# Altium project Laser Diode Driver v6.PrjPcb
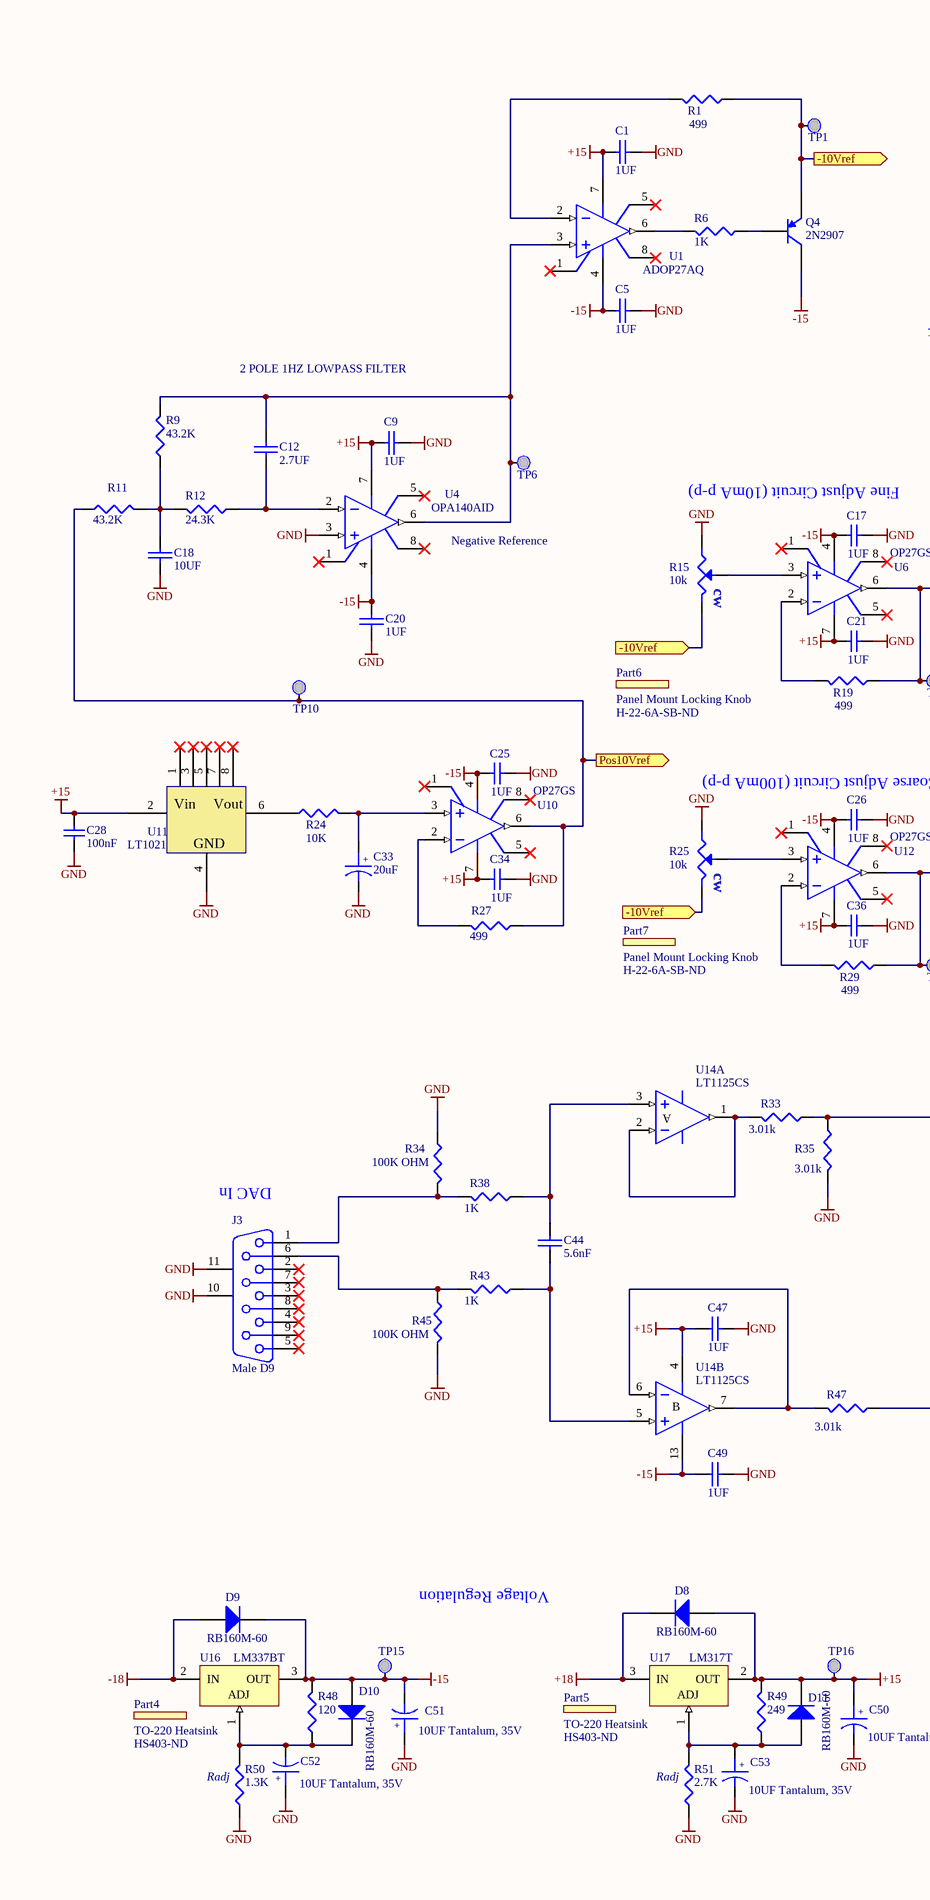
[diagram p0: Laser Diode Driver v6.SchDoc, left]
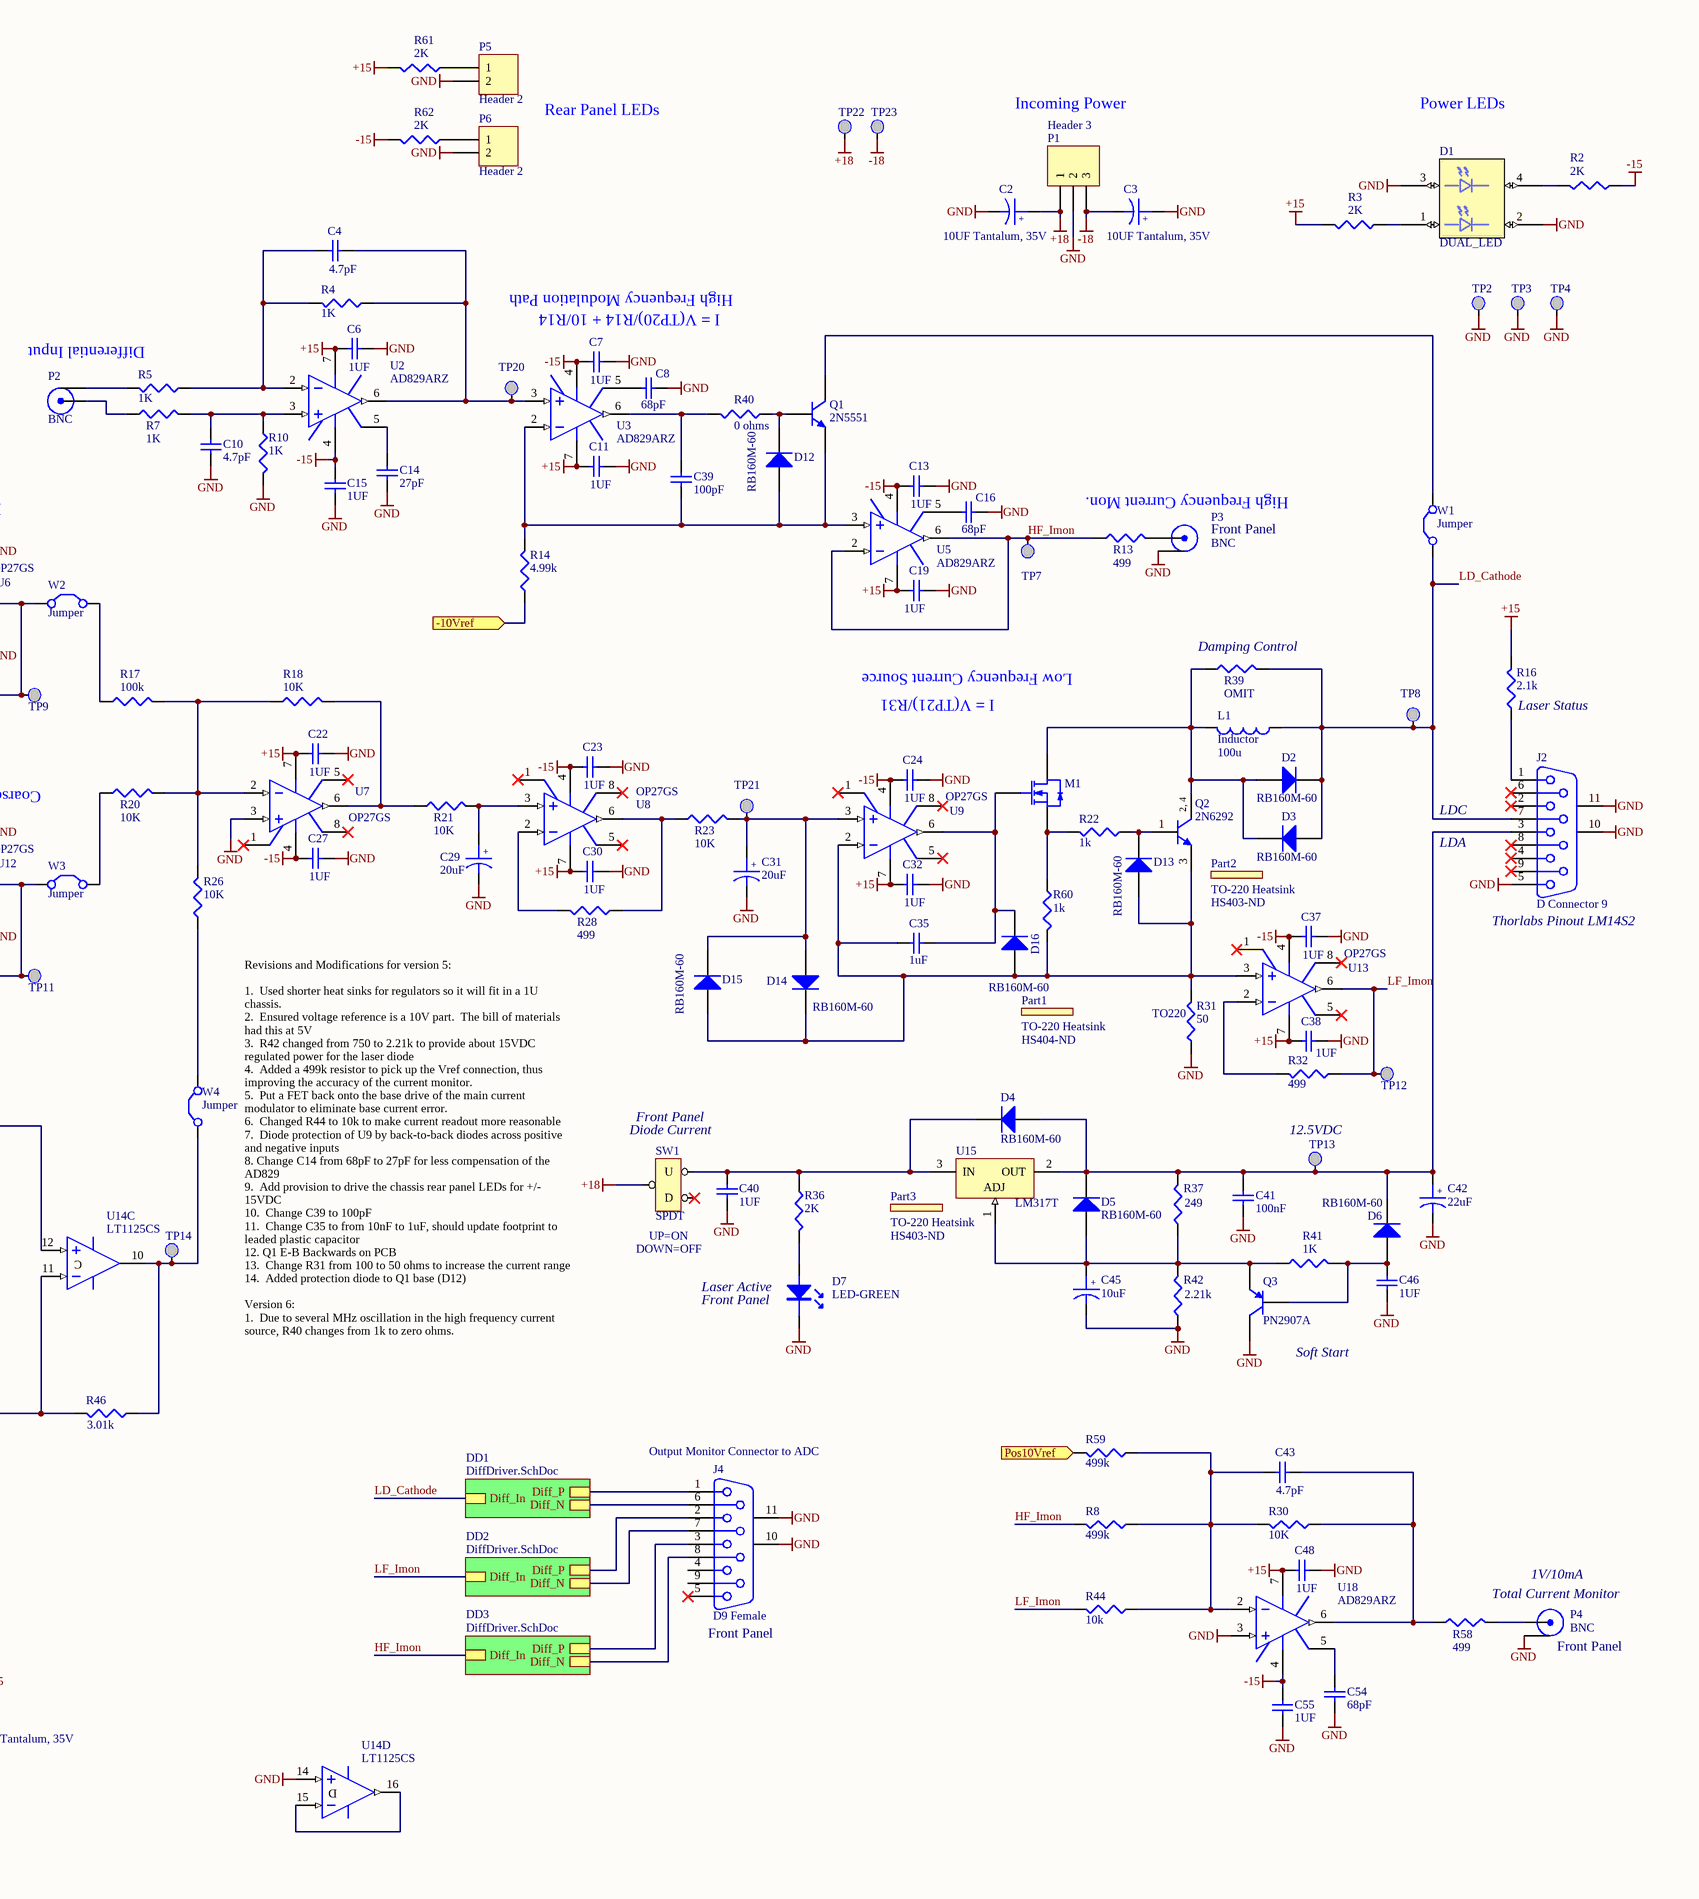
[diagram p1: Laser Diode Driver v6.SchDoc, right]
2 sheets, 224 parts. Net scope: hierarchical (ports join the sheet entries above them; power ports are global).
Board file: Laser Diode Driver v5.PcbDoc
Sheets:
  Laser Diode Driver v6.SchDoc
    DD1 = DiffDriver.SchDoc
    DD2 = DiffDriver.SchDoc
    DD3 = DiffDriver.SchDoc

## Sheet Laser Diode Driver v6.SchDoc: Laser Current Driver
size C; PageSetup: Record=PageOptions|CenterHorizontal=True|CenterVertical=True|PrintScale=0.70|XCorrection=1.00|YCorrection=1.00|PrintKind=0|BorderSize=5000000|LeftOffset=0|BottomOffset=0|Orientation=2|PaperLength=1000|PaperWidth=1000|Scale=100|PaperSource=15|PrintQuality=600|MediaType=1|DitherType=10|PaperKind=11x17|PrintScaleMode=1; Organization: LIGO Laboratory; Address1: California Institute of Technology; Address2: Massachusetts Institute of Technology; DocumentNumber: D1200719; Revision: V5; SheetNumber: 1; SheetTotal: 2; Engineer: R.S. Abbott

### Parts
C1  1UF  [3216[1206]]
C2  10UF Tantalum, 35V  [7343-31]
C3  10UF Tantalum, 35V  [7343-31]
C4  4.7pF  [3216[1206]]
C5  1UF  [3216[1206]]
C6  1UF  [3216[1206]]
C7  1UF  [3216[1206]]
C8  68pF  [3216[1206]]
C9  1UF  [3216[1206]]
C10  4.7pF  [3216[1206]]
C11  1UF  [3216[1206]]
C12  2.7UF  [ECQ-E1275KF]
C13  1UF  [3216[1206]]
C14  27pF  [3216[1206]]
C15  1UF  [3216[1206]]
C16  68pF  [3216[1206]]
C17  1UF  [3216[1206]]
C18  10UF  [ECQ-E1106KF_Side]
C19  1UF  [3216[1206]]
C20  1UF  [3216[1206]]
C21  1UF  [3216[1206]]
C22  1UF  [3216[1206]]
C23  1UF  [3216[1206]]
C24  1UF  [3216[1206]]
C25  1UF  [3216[1206]]
C26  1UF  [3216[1206]]
C27  1UF  [3216[1206]]
C28  100nF  [3216[1206]]
C29  20uF  [AmCap_20UF]
C30  1UF  [3216[1206]]
C31  20uF  [AmCap_20UF]
C32  1UF  [3216[1206]]
C33  20uF  [AmCap_20UF]
C34  1UF  [3216[1206]]
C35  1uF  [ECQ-E1105KF]
C36  1UF  [3216[1206]]
C37  1UF  [3216[1206]]
C38  1UF  [3216[1206]]
C39  100pF  [3216[1206]]
C40  1UF  [3216[1206]]
C41  100nF  [3216[1206]]
C42  22uF  [7343-31]
C43  4.7pF  [3216[1206]]
C44  5.6nF  [3216[1206]]
C45  10uF  [7343-31]
C46  1UF  [3216[1206]]
C47  1UF  [3216[1206]]
C48  1UF  [3216[1206]]
C49  1UF  [3216[1206]]
C50  10UF Tantalum, 35V  [6032]
C51  10UF Tantalum, 35V  [6032]
C52  10UF Tantalum, 35V  [6032]
C53  10UF Tantalum, 35V  [6032]
C54  68pF  [3216[1206]]
C55  1UF  [3216[1206]]
D1  DUAL_LED  [my LUMEX Dual LED]
D2  RB160M-60  [SOD123]
D3  RB160M-60  [SOD123]
D4  RB160M-60  [SOD123]
D5  RB160M-60  [SOD123]
D6  RB160M-60  [SOD123]
D7  LED-GREEN  [LED_RA]
D8  RB160M-60  [SOD123]
D9  RB160M-60  [SOD123]
D10  RB160M-60  [SOD123]
D11  RB160M-60  [SOD123]
D12  RB160M-60  [SOD123]
D13  RB160M-60  [SOD123]
D14  RB160M-60  [SOD123]
D15  RB160M-60  [SOD123]
D16  RB160M-60  [SOD123]
J2  D Connector 9  [MY_DB9F_RA]
J3  Male D9  [MY_DB9M_RA]
J4  D9 Female  [MY_DB9F_RA]
L1  Inductor  value 100u  [CDRH127]
M1  NMOS  [SOT416-3L]  (value not drawn)
P1  Header 3  [Molex_156_RA_3]
P2  BNC  [MY_BNC_RA CON]
P3  BNC  [MY_BNC_RA CON]
P4  BNC  [MY_BNC_RA CON]
P5  Header 2  [MOLEX_156_RA_2]
P6  Header 2  [MOLEX_156_RA_2]
Part1  TO-220 Heatsink  Digikey Part Number: HS404-ND  (mechanical)
Part2  TO-220 Heatsink  Digikey Part Number: HS403-ND  (mechanical)
Part3  TO-220 Heatsink  Digikey Part Number: HS403-ND  (mechanical)
Part4  TO-220 Heatsink  Digikey Part Number: HS403-ND  (mechanical)
Part5  TO-220 Heatsink  Digikey Part Number: HS403-ND  (mechanical)
Part6  Panel Mount Locking Knob  Digikey Part Number: H-22-6A-SB-ND  (mechanical)
Part7  Panel Mount Locking Knob  Digikey Part Number: H-22-6A-SB-ND  (mechanical)
Q1  2N5551  [SOT-23]
Q2  2N6292  [HS403-ND]
Q3  PN2907A  [sot-23 3906]
Q4  2N2907  [sot-23 3906]
R1  499  [3216[1206]]
R2  2K  [3216[1206]]
R3  2K  [3216[1206]]
R4  1K  [3216[1206]]
R5  1K  [3216[1206]]
R6  1K  [3216[1206]]
R7  1K  [3216[1206]]
R8  499k  [3216[1206]]
R9  43.2K  [3216[1206]]
R10  1K  [3216[1206]]
R11  43.2K  [3216[1206]]
R12  24.3K  [3216[1206]]
R13  499  [3216[1206]]
R14  4.99k  [3216[1206]]
R15  10k  [Bournes Pot]
R16  2.1k  [3216[1206]]
R17  100k  [3216[1206]]
R18  10K  [3216[1206]]
R19  499  [3216[1206]]
R20  10K  [3216[1206]]
R21  10K  [3216[1206]]
R22  1k  [3216[1206]]
R23  10K  [3216[1206]]
R24  10K  [3216[1206]]
R25  10k  [Bournes Pot]
R26  10K  [3216[1206]]
R27  499  [3216[1206]]
R28  499  [3216[1206]]
R29  499  [3216[1206]]
R30  10K  [3216[1206]]
R31  value 50  [AAVID TO220 Heatsink_2pin]  (hidden comment: Res3)
R32  499  [3216[1206]]
R33  3.01k  [3216[1206]]
R34  100K OHM  [3216[1206]]
R35  3.01k  [3216[1206]]
R36  2K  [3216[1206]]
R37  249  [3216[1206]]
R38  1K  [3216[1206]]
R39  OMIT  [3216[1206]]
R40  0 ohms  [3216[1206]]
R41  1K  [3216[1206]]
R42  2.21k  [3216[1206]]
R43  1K  [3216[1206]]
R44  10k  [3216[1206]]
R45  100K OHM  [3216[1206]]
R46  3.01k  [3216[1206]]
R47  3.01k  [3216[1206]]
R48  120  [3216[1206]]
R49  249  [3216[1206]]
R50  1.3K  [3216[1206]]
R51  2.7K  [3216[1206]]
R58  499  [3216[1206]]
R59  499k  [3216[1206]]
R60  1k  [3216[1206]]
R61  2K  [3216[1206]]
R62  2K  [3216[1206]]
SW1  SPDT  [my_ra_spdt]
TP1  TESTPT  [smt_tp]  (value not drawn)
TP2  TESTPT  [smt_tp]  (value not drawn)
TP3  TESTPT  [smt_tp]  (value not drawn)
TP4  TESTPT  [smt_tp]  (value not drawn)
TP6  TESTPT  [smt_tp]  (value not drawn)
TP7  TESTPT  [smt_tp]  (value not drawn)
TP8  TESTPT  [smt_tp]  (value not drawn)
TP9  TESTPT  [smt_tp]  (value not drawn)
TP10  TESTPT  [smt_tp]  (value not drawn)
TP11  TESTPT  [smt_tp]  (value not drawn)
TP12  TESTPT  [smt_tp]  (value not drawn)
TP13  TESTPT  [smt_tp]  (value not drawn)
TP14  TESTPT  [smt_tp]  (value not drawn)
TP15  TESTPT  [smt_tp]  (value not drawn)
TP16  TESTPT  [smt_tp]  (value not drawn)
TP20  TESTPT  [smt_tp]  (value not drawn)
TP21  TESTPT  [smt_tp]  (value not drawn)
TP22  TESTPT  [smt_tp]  (value not drawn)
TP23  TESTPT  [smt_tp]  (value not drawn)
U1  ADOP27AQ  [SO8_M]
U2  value AD829ARZ  [SOIC127P600-8N]  (hidden comment: AD829)
U3  value AD829ARZ  [SOIC127P600-8N]  (hidden comment: AD829)
U4  OPA140AID  [SO8_M]
U5  value AD829ARZ  [SOIC127P600-8N]  (hidden comment: AD829)
U6  OP27GS  [SO-8_N]
U7  OP27GS  [SO-8_N]
U8  OP27GS  [SO-8_N]
U9  OP27GS  [SO-8_N]
U10  OP27GS  [SO-8_N]
U11  LT1021  [SO-8]
U12  OP27GS  [SO-8_N]
U13  OP27GS  [SO-8_N]
U14  LT1125CS  [SOIC127P1030-16N]  (parts A,B,C,D of 4)
U15  LM317T  [HS403-ND]
U16  LM337BT  [HS403-ND]
U17  LM317T  [HS403-ND]
U18  value AD829ARZ  [SOIC127P600-8N]  (hidden comment: AD829)
W1  Jumper  [HDR1X3]
W2  Jumper  [HDR1X3]
W3  Jumper  [HDR1X3]
W4  Jumper  [HDR1X3]

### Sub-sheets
DD1 = DiffDriver.SchDoc: Diff_P, Diff_N, Diff_In
DD2 = DiffDriver.SchDoc: Diff_P, Diff_N, Diff_In
DD3 = DiffDriver.SchDoc: Diff_P, Diff_N, Diff_In

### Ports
-10Vref, Pos10Vref

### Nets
+15: C1.2 C6.2 C9.1 C11.2 C19.2 C21.2 C22.2 C28.2 C30.2 C32.2 C34.2 C36.2 C38.2 C47.1 C48.2 C50.1 D8.1(A) D11.2(K) R3.2 R16.2 R49.2 R61.2 TP16.1 U1.7(V+) U2.7(V+) U3.7(V+) U4.7(V+) U5.7(V+) U6.7(V+) U7.7(V+) U8.7(V+) U9.7(V+) U10.7(V+) U11.2 U12.7(V+) U13.7(V+) U14.4(V+) U17.2(OUT) U18.7(V+)
+18: C2.1 D8.2(K) P1.1 SW1.2 TP22.1 U17.3(IN)
-15: C5.2 C7.2 C13.2 C15.2 C17.2 C20.1 C23.2 C24.2 C25.2 C26.2 C27.2 C37.2 C49.1 C51.2 C55.2 D9.2(K) D10.1(A) Q4.3(C) R2.1 R48.2 R62.2 TP15.1 U1.4(V-) U2.4(V-) U3.4(V-) U4.4(V-) U5.4(V-) U6.4(V-) U7.4(V-) U8.4(V-) U9.4(V-) U10.4(V-) U12.4(V-) U13.4(V-) U14.13(V-) U16.3(OUT) U18.4(V-)
-18: C3.2 D9.1(A) P1.3 TP23.1 U16.2(IN)
GND: C1.1 C2.2 C3.1 C5.1 C6.1 C7.1 C8.1 C9.2 C10.1 C11.1 C13.1 C14.1 C15.1 C16.1 C17.1 C18.2 C19.1 C20.2 C21.1 C22.1 C23.1 C24.1 C25.1 C26.1 C27.1 C28.1 C29.2 C30.1 C31.2 C32.1 C33.2 C34.1 C36.1 C37.1 C38.1 C40.2 C41.2 C42.2 C45.2 C46.2 C47.2 C48.1 C49.2 C50.2 C51.1 C52.1 C53.2 C54.1 C55.1 D1.2 D1.3 D7.K J2.5 J2.10(MH1) J2.11(MH2) J3.10(MH1) J3.11(MH2) J4.10(MH1) J4.11(MH2) P1.2 P3.2 P4.2 P5.2 P6.2 Q3.3(C) R10.2 R15.1 R25.1 R31.1 R34.1 R35.2 R42.1 R45.2 R50.1 R51.1 TP2.1 TP3.1 TP4.1 U4.3(IN+) U7.3(IN+) U11.4 U14.14(IN+) U18.3(IN+)
HF_Imon: R8.2 R13.1 TP7.1 U5.2(IN-) U5.6(OUT) ; sheet DD3/Diff_In
LD_Cathode: D2.2(K) D3.1(A) J2.7 L1.1 R39.2 TP8.1 W1.1(C1) ; sheet DD1/Diff_In
LF_Imon: R32.1 R44.2 TP12.1 U13.6(OUT) ; sheet DD2/Diff_In
NetC4_1: C4.1 R4.1 TP20.1 U2.6(OUT) U3.3(IN+)
NetC4_2: C4.2 R4.2 R5.1 U2.2(IN-)
NetC8_2: C8.2 U3.5(NUL)
NetC10_2: C10.2 R7.2 R10.1 U2.3(IN+)
NetC12_1: C12.1 R9.2 TP6.1 U1.3(IN+) U4.6(OUT)
NetC12_2: C12.2 R12.1 U4.2(IN-)
NetC14_2: C14.2 U2.5(NUL)
NetC16_2: C16.2 U5.5(NUL)
NetC18_1: C18.1 R9.1 R11.2 R12.2
NetC29_1: C29.1 R21.2 U8.3(IN+)
NetC31_1: C31.1 D14.1(A) D15.2(K) R23.2 TP21.1 U9.3(IN+)
NetC33_1: C33.1 R24.2 U10.3(IN+)
NetC35_1: C35.1 D13.1(A) D14.2(K) D15.1(A) D16.1(A) Q2.3(E) R31.2 R60.2 U9.2(IN-) U13.3(IN+)
NetC35_2: C35.2 D16.2(K) M1.1(G) U9.6(OUT)
NetC39_1: C39.1 R40.2 U3.6(OUT)
NetC39_2: C39.2 D12.1(A) Q1.2(E) R14.2 U3.2(IN-) U5.3(IN+)
NetC40_1: C40.1 D4.2(K) R36.1 SW1.1(U) U15.3(IN)
NetC41_1: C41.1 C42.1 D4.1(A) D5.2(K) D6.2(K) J2.3 R37.2 TP13.1 U15.2(OUT)
NetC43_1: C43.1 R30.1 R58.1 U18.6(OUT)
NetC43_2: C43.2 R8.1 R30.2 R44.1 R59.1 U18.2(IN-)
NetC44_1: C44.1 R43.1 U14.5(IN+)
NetC44_2: C44.2 R38.1 U14.3(IN+)
NetC45_1: C45.1 D5.1(A) Q3.1(E) R37.1 R41.1 R42.2 U15.1(ADJ)
NetC46_1: C46.1 D6.1(A) Q3.2(B) R41.2
NetC52_2: C52.2 D10.2(K) R48.1 R50.2 U16.1(ADJ)
NetC53_1: C53.1 D11.1(A) R49.1 R51.2 U17.1(ADJ)
NetC54_2: C54.2 U18.5(NUL)
NetD1_1: D1.1 R3.1
NetD1_4: D1.4 R2.2
NetD2_1: D2.1(A) D3.2(K) L1.2 M1.3(D) Q2.2(C) R39.1
NetD7_A: D7.A R36.2
NetD12_2: D12.2(K) Q1.1(B) R40.1
NetD13_2: D13.2(K) Q2.1(B) R22.1
NetJ2_1: J2.1 R16.1
NetJ3_1: J3.1 R34.2 R38.2
NetJ3_6: J3.6 R43.2 R45.1
NetJ4_1: J4.1 ; sheet DD1/Diff_P
NetJ4_2: J4.2 ; sheet DD2/Diff_P
NetJ4_3: J4.3 ; sheet DD3/Diff_P
NetJ4_6: J4.6 ; sheet DD1/Diff_N
NetJ4_7: J4.7 ; sheet DD2/Diff_N
NetJ4_8: J4.8 ; sheet DD3/Diff_N
NetM1_2: M1.2(S) R22.2 R60.1
NetP2_1: P2.1 R7.1
NetP2_2: P2.2 R5.2
NetP3_1: P3.1 R13.2
NetP4_1: P4.1 R58.2
NetP5_1: P5.1 R61.1
NetP6_1: P6.1 R62.1
NetQ1_3: Q1.3(C) W1.2(C2)
NetQ4_1: Q4.1(E) R1.1 R14.1 R15.3 R25.3 TP1.1 ; port -10Vref
NetQ4_2: Q4.2(B) R6.1
NetR1_2: R1.2 U1.2(IN-)
NetR6_2: R6.2 U1.6(OUT)
NetR11_1: R11.1 R27.1 R59.2 TP10.1 U10.6(OUT) ; port Pos10Vref
NetR15_2: R15.2 U6.3(IN+)
NetR17_1: R17.1 W2.2(C2)
NetR17_2: R17.2 R18.1 R20.2 R26.2 U7.2(IN-)
NetR18_2: R18.2 R21.1 U7.6(OUT)
NetR19_1: R19.1 TP9.1 U6.6(OUT) W2.1(C1)
NetR19_2: R19.2 U6.2(IN-)
NetR20_1: R20.1 W3.2(C2)
NetR23_1: R23.1 R28.1 U8.6(OUT)
NetR24_1: R24.1 U11.6
NetR25_2: R25.2 U12.3(IN+)
NetR26_1: R26.1 W4.2(C2)
NetR27_2: R27.2 U10.2(IN-)
NetR28_2: R28.2 U8.2(IN-)
NetR29_1: R29.1 TP11.1 U12.6(OUT) W3.1(C1)
NetR29_2: R29.2 U12.2(IN-)
NetR32_2: R32.2 U13.2(IN-)
NetR33_1: R33.1 R35.1 U14.12(IN+)
NetR33_2: R33.2 U14.1(OUT) U14.2(IN-)
NetR46_1: R46.1 TP14.1 U14.10(OUT) W4.1(C1)
NetR46_2: R46.2 R47.1 U14.11(IN-)
NetR47_2: R47.2 U14.6(IN-) U14.7(OUT)
NetU14_15: U14.15(IN-) U14.16(OUT)

Not connected (* = marked no-connect by the designer): J2 2* 4* 6* 8* 9*; J3 2* 3* 4* 5* 7* 8* 9*; J4 4 5* 9; SW1 3(D)*; U1 1(NULL1)* 5(NC)* 8(NULL2)*; U2 1(NUL) 8(NC); U3 1(NUL) 8(NC); U4 1(NULL1)* 5(NC)* 8(NULL2)*; U5 1(NUL) 8(NC); U6 1(CMPEN)* 5(NC)* 8(CMPEN)*; U7 1(CMPEN)* 5(NC)* 8(CMPEN)*; U8 1(CMPEN)* 5(NC)* 8(CMPEN)*; U9 1(CMPEN)* 5(NC)* 8(CMPEN)*; U10 1(CMPEN)* 5(NC)* 8(CMPEN)*; U11 1* 3* 5* 7* 8*; U12 1(CMPEN)* 5(NC)* 8(CMPEN)*; U13 1(CMPEN)* 5(NC)* 8(CMPEN)*; U18 1(NUL) 8(NC)

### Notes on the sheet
- Rear Panel LEDs
- Incoming Power
- Power LEDs
- (near C7) I = V(TP20)/R14 + 10/R14
- High Frequency Modulation Path
- 2 POLE 1HZ LOWPASS FILTER
- Differential Input
- Fine Adjust Circuit (10mA p-p)
- (near P3) Front Panel
- High Frequency Current Mon.
- Negative Reference
- Low Frequency Current Source
- (near R39) Damping Control
- I = V(TP21)/R31
- (near R16) Laser Status
- Coarse Adjust Circuit (100mA p-p)
- LDC
- LDA
- (near J2) Thorlabs Pinout LM14S2
- (near J3) DAC In
- Diode Current
- Front Panel
- (near TP13) 12.5VDC
- (near SW1) UP=ON
- DOWN=OFF
- (near D7) Front Panel
- (near D7) Laser Active
- Revisions and Modifications for version 5:
  1.  Used shorter heat sinks for regulators so it will fit in a 1U chassis.
  2.  Ensured voltage reference is a 10V part.  The bill of materials had this at 5V
  3.  R42 changed from 750 to 2.21k to provide about 15VDC regulated power for the laser diode
  4.  Added a 499k resistor to pick up the Vref connection, thus improving the accuracy of the current monitor.
  5.  Put a FET back onto the base drive of the main current modulator to eliminate base current error.
  6.  Changed R44 to 10k to make current readout more reasonable
  7.  Diode protection of U9 by back-to-back diodes across positive and negative inputs
  8. Change C14 from 68pF to 27pF for less compensation of the AD829
  9.  Add provision to drive the chassis rear panel LEDs for +/- 15VDC
  10.  Change C39 to 100pF
  11.  Change C35 to from 10nF to 1uF, should update footprint to leaded plastic capacitor
  12. Q1 E-B Backwards on PCB
  13.  Change R31 from 100 to 50 ohms to increase the current range
  14.  Added protection diode to Q1 base (D12)
  Version 6:
  1.  Due to several MHz oscillation in the high frequency current source, R40 changes from 1k to zero ohms.
- Soft Start
- (near J4) Output Monitor Connector to ADC
- 1V/10mA
- Voltage Regulation
- (near J4) Front Panel
- Total Current Monitor
- (near P4) Front Panel
- (near R50) Radj
- (near R51) Radj

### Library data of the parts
C1 C5 C9 C12 C18 C20 = MYCAP: Checked: y
C2 C3 = CAPACITOR POL: Polarized Cap; Manufacturer: AVX Corporation; Manufacturers Part Number: TAJC106K035RNJ; Description: CAP TANTALUM 10UF 35V 10% SMD; Capacitance: 10µF; Checked: y
C4 C8 C10 C14 C16 C28 C35 C39 C43 C54 = Cap: Capacitor; Checked: y
C6 C7 C11 C13 C15 C17 C19 C21-C27 C30 C32 C34 C36-C38 C40 C46 C48 C55 = Cap: Capacitor; Checked: y; Capacitance: 1.0µF
C29 C31 C33 C42 = CAPACITOR POL: Polarized Cap; Checked: y
C41 = Cap: Capacitor
C44 = MYCAP: CAP 1.0UF 50V CERAMIC F 1206; Checked: y
C45 = CAPACITOR POL: Polarized Cap; Manufacturer: AVX Corporation; Manufacturers Part Number: TAJC106M035RNJ; Checked: y; Capacitance: 10µF
C47 C49 = MYCAP: CAP 1.0UF 50V CERAMIC F 1206; Capacitance: 1.0µF; Checked: y
C50-C53 = CAPACITOR POL: Polarized Cap; Manufacturer: AVX Corporation; Manufacturers Part Number: TAJC106M035RNJ; Description: CAP TANTALUM 10UF 35V 10% SMD; Capacitance: 10µF; Checked: y
D1 = DUAL_LED: Dual Led indicator; Checked: y
D2-D6 D12-D16 = Diode 1N4001: 1 Amp General Purpose Rectifier; Checked: y
D7 = LED: LED GREEN T1-3/4 RT ANG PCB; Checked: y
D8-D11 = Diode 1N4148: High Conductance Fast Diode; Checked: y
J2-J4 = D Connector 9: Receptacle Assembly, 9 Position, Right Angle; Checked: y
L1 = Inductor: Checked: n
M1 = 2SK3019: ROHM N-Channel MOSFET; Checked: n
P1 = Header 3: Header, 3-Pin; Checked: y
P2-P4 = BNC: Checked: y
P5 P6 = Header 2: Header, 2-Pin; Checked: y
Part1 = Mechanical Part: For BOM Only
Part2-Part7 = Mechanical Part: For BOM Only; Checked: y
Q1 = 2N5551: NPN General Purpose Amplifier; Checked: y
Q2 = FZT649: SOT223 NPN Silicon Planar High-Performance Transistor; Checked: y
Q3 = PN2907A: PNP General Purpose Amplifier; Checked: y
Q4 = 2N3906: PNP General Purpose Amplifier; Checked: y
R1-R14 R16-R24 R26-R30 R32 R36 R37 R39-R42 R44 R58-R62 = Res3: Resistor; Checked: y
R15 R25 = MPEPOT: Potentiometer; Checked: y
R31 = Res3: Resistor; Heatsink Part Number: HS404-ND; Checked: y
R33 R47 = MYRES: Resistor; Description: RES 3.01K OHM 1/4W 1% 1206 SMD; Checked: y
R34 R45 = MYRES: Resistor; Description: RES 100K OHM 1/4W .1% 1206 SMD; Checked: y
R35 R46 = MYRES: Resistor; Description: RES 1.50K OHM 1/4W 0.1% 1206; Checked: y
R38 = MYRES: Resistor; Description: VISHAY DALE - WSL120600000ZEA9 - RESISTOR, ZERO OHM JUMPER; Checked: y
R43 = MYRES: Resistor; Manufacturer: VISHAY DALE; Manufacturers Part Number: WSL120600000ZEA9; Description: VISHAY DALE - WSL120600000ZEA9 - RESISTOR, ZERO OHM JUMPER; Checked: y
R48-R51 = MYRES: Checked: y
SW1 = MY_SPDT: Rocker SPDT; Checked: y
TP1-TP4 TP6-TP16 TP20-TP23 = TESTPT: PCB Testpoint; Checked: y
U1 = ADOP27AQ: Ultra-Low Noise, Precision Operational Amplifier; Checked: y
U2 U3 U5 U18 = OP184ES: Video Operational Amplifier; Manufacturer: Analog Devices Inc; Description: IC VIDEO OPAMP HS LN 8-SOIC; Checked: y
U4 = ADOP27AQ: FET Input Operational Amplifier; Checked: y
U6-U10 U12 U13 = OP27GS: Low-Noise, Precision Operational Amplifier; Checked: y
U11 = LT1021: Precision Voltage Reference; Checked: y
U14 = LT1125CS: Quad Low Noise, High-Speed Precision Operational Amplifier; Manufacturer: LINEAR TECHNOLOGY; Manufacturers Part Number: LT1125CSW#PBF; Description: LINEAR TECHNOLOGY - LT1125CSW#PBF - IC, OP-AMP, 12.5MHZ, 4.5V/µS, SOIC-16; Checked: y
U15 U17 = LM317T: Three-Terminal Adjustable Output Positive Voltage Regulator; Checked: n
U16 = LM337BT: 3-Terminal Adjustable Negative Voltage Regulator; Checked: y
W1-W4 = Jumper: Jumper Wire; Checked: y

## Sheet DiffDriver.SchDoc: Differential Driver
size A; Organization: LIGO Laboratory; Address1: California Institute of Technology; Address2: Massachusetts Institute of Technology; Revision: V5; SheetNumber: 2; SheetTotal: 2; Engineer: R.S. Abbott
Used 3 times, as channels DD1, DD2, DD3. Parts and nets are listed once, with the designators drawn on the sheet.
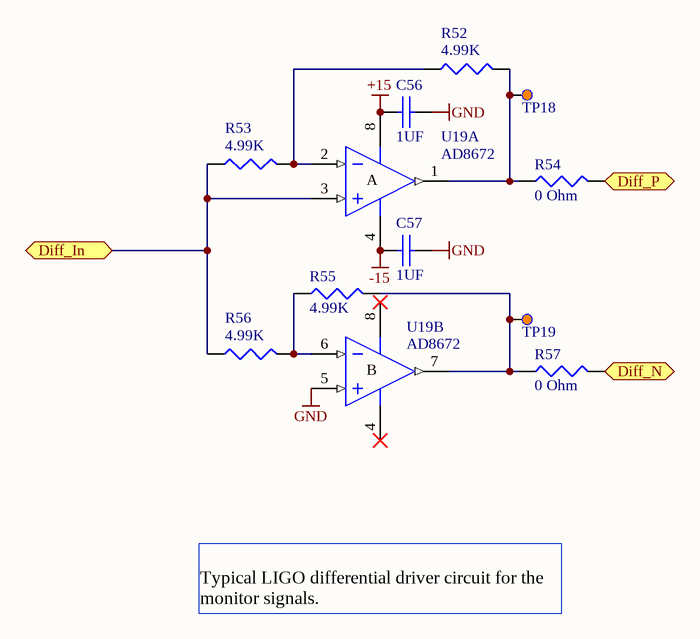
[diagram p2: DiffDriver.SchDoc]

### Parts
C56  1UF  [3216[1206]]
C57  1UF  [3216[1206]]
R52  4.99K  [3216[1206]]
R53  4.99K  [3216[1206]]
R54  0 Ohm  [3216[1206]]
R55  4.99K  [3216[1206]]
R56  4.99K  [3216[1206]]
R57  0 Ohm  [3216[1206]]
TP18  Wire Hole  [TP-hole]  (value not drawn)  (no BOM)
TP19  Wire Hole  [TP-hole]  (value not drawn)  (no BOM)
U19  AD8672  [SO8_N]  (parts A,B of 2)

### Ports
Diff_In, Diff_N, Diff_P

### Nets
+15: C56.2 U19.8(V+)
-15: C57.2 U19.4(V-)
GND: C56.1 C57.1 U19.5(IN+)
Diff_In: R53.1 R56.1 U19.3(IN+) ; port Diff_In
Diff_N: R57.2 ; port Diff_N
Diff_P: R54.2 ; port Diff_P
NetR52_1: R52.1 R53.2 U19.2(IN-)
NetR52_2: R52.2 R54.1 TP18.1 U19.1(OUT)
NetR55_1: R55.1 R56.2 U19.6(IN-)
NetR55_2: R55.2 R57.1 TP19.1 U19.7(OUT)

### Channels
DD1: designators end in _DD1; ports Diff_In=LD_Cathode Diff_N=NetJ4_6 Diff_P=NetJ4_1
DD2: designators end in _DD2; ports Diff_In=LF_Imon Diff_N=NetJ4_7 Diff_P=NetJ4_2
DD3: designators end in _DD3; ports Diff_In=HF_Imon Diff_N=NetJ4_8 Diff_P=NetJ4_3

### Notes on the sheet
- Typical LIGO differential driver circuit for the monitor signals.

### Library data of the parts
C56 C57 = MYCAP: Checked: y
R52-R57 = Res3: Resistor; Checked: y
TP18 TP19 = TestHole: Plated Hole to Solder Wire to; Checked: y
U19 = AD826AR: High-Speed, Low-Power Dual Operational Amplifier; Checked: y

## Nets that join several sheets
+15: Laser Diode Driver v6 (39 pins), DD1 (C56_DD1.2 U19_DD1.8), DD2 (C56_DD2.2 U19_DD2.8), DD3 (C56_DD3.2 U19_DD3.8)
-15: Laser Diode Driver v6 (37 pins), DD1 (C57_DD1.2 U19_DD1.4), DD2 (C57_DD2.2 U19_DD2.4), DD3 (C57_DD3.2 U19_DD3.4)
GND: Laser Diode Driver v6 (83 pins), DD1 (C56_DD1.1 C57_DD1.1 U19_DD1.5), DD2 (C56_DD2.1 C57_DD2.1 U19_DD2.5), DD3 (C56_DD3.1 C57_DD3.1 U19_DD3.5)
HF_Imon: Laser Diode Driver v6 (5 pins), DD3 (R53_DD3.1 R56_DD3.1 U19_DD3.3)
LD_Cathode: Laser Diode Driver v6 (7 pins), DD1 (R53_DD1.1 R56_DD1.1 U19_DD1.3)
LF_Imon: Laser Diode Driver v6 (R32.1 R44.2 TP12.1 U13.6), DD2 (R53_DD2.1 R56_DD2.1 U19_DD2.3)
NetJ4_1: Laser Diode Driver v6 (J4.1), DD1 (R54_DD1.2)
NetJ4_2: Laser Diode Driver v6 (J4.2), DD2 (R54_DD2.2)
NetJ4_3: Laser Diode Driver v6 (J4.3), DD3 (R54_DD3.2)
NetJ4_6: Laser Diode Driver v6 (J4.6), DD1 (R57_DD1.2)
NetJ4_7: Laser Diode Driver v6 (J4.7), DD2 (R57_DD2.2)
NetJ4_8: Laser Diode Driver v6 (J4.8), DD3 (R57_DD3.2)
